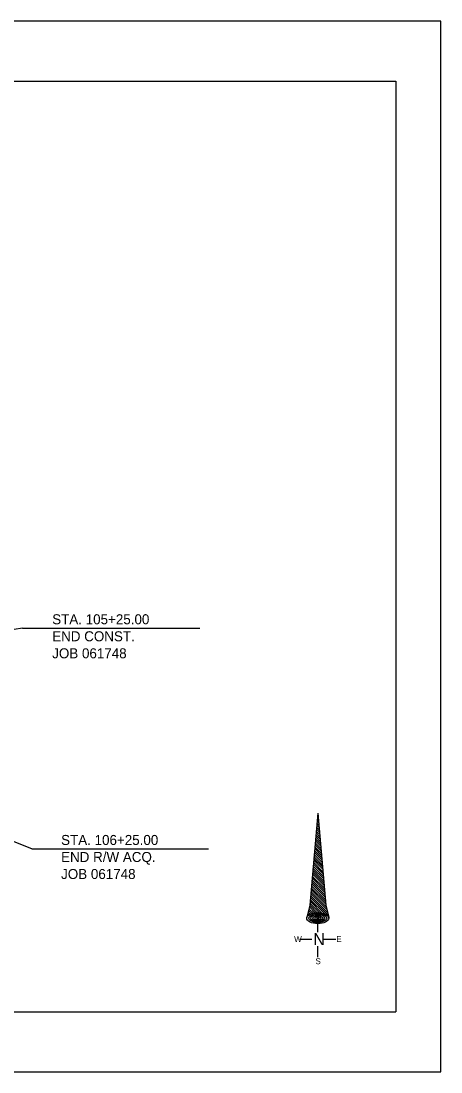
# Model space of a CAD drawing. Extents: x -3711 to 825, y -151 to 1050.
# Drawn here: x -2480 to -2061, y 0 to 1050 of the extents above; entities that cross this region are included whole.
import ezdxf

# ---------------------------------------------------------------- set-up
doc = ezdxf.new("R2010")
doc.units = 0
for name, color, linetype in [('E_Sheet Border', 7, 'Continuous'), ('E_Title Sheet', 7, 'Continuous'), ('R_Dimension', 7, 'Continuous'), ('R_No Plot', 7, 'Continuous')]:
    doc.layers.add(name, color=color, linetype=linetype)

msp = doc.modelspace()

# ---------------------------------------------------------------- linework, layer by layer
at = {"layer": 'E_Sheet Border'}
msp.add_lwpolyline([(-3710.7, 0), (-2060.7, 0), (-2060.7, 1050), (-3710.7, 1050)], close=True, dxfattribs=at)
at = {"layer": 'E_Title Sheet'}
for p, q in [((-2183.7, 258.7), (-2191.7, 166.7)), ((-2184.2, 252.4), (-2183, 251.3)), ((-2184.1, 254.4), (-2183.3, 253.6)), ((-2183.9, 256.3), (-2183.5, 255.9)), ((-2183.7, 258.7), (-2175.7, 166.7)), ((-2183.7, 258.3), (-2183.7, 258.2)), ((-2185.1, 242.7), (-2182, 239.6)), ((-2184.9, 244.6), (-2182.2, 242)), ((-2184.7, 246.6), (-2182.4, 244.3)), ((-2184.6, 248.5), (-2182.6, 246.6)), ((-2184.4, 250.5), (-2182.8, 248.9)), ((-2185.9, 232.9), (-2181, 228)), ((-2185.8, 234.9), (-2181.2, 230.3)), ((-2185.6, 236.8), (-2181.4, 232.7)), ((-2185.4, 238.8), (-2181.6, 235)), ((-2185.3, 240.7), (-2181.8, 237.3)), ((-2186.9, 221.2), (-2179.8, 214.1)), ((-2186.8, 223.2), (-2180, 216.4)), ((-2186.6, 225.1), (-2180.2, 218.7)), ((-2186.4, 227.1), (-2180.4, 221.1)), ((-2186.3, 229), (-2180.6, 223.4)), ((-2186.1, 231), (-2180.8, 225.7)), ((-2187.8, 211.5), (-2178.8, 202.5)), ((-2187.6, 213.4), (-2179, 204.8)), ((-2187.5, 215.4), (-2179.2, 207.1)), ((-2187.3, 217.3), (-2179.4, 209.4)), ((-2187.1, 219.3), (-2179.6, 211.8)), ((-2188.8, 199.7), (-2177.6, 188.5)), ((-2188.6, 201.7), (-2177.8, 190.8)), ((-2188.5, 203.7), (-2178, 193.2)), ((-2188.3, 205.6), (-2178.2, 195.5)), ((-2188.1, 207.6), (-2178.4, 197.8)), ((-2188, 209.5), (-2178.6, 200.1)), ((-2189.7, 190), (-2176.6, 176.9)), ((-2189.5, 191.9), (-2176.8, 179.2)), ((-2189.3, 193.9), (-2177, 181.6)), ((-2189.2, 195.8), (-2177.2, 183.9)), ((-2189, 197.8), (-2177.4, 186.2)), ((-2190.5, 180.2), (-2175.3, 165)), ((-2190.3, 182.2), (-2175.8, 167.6)), ((-2190.2, 184.1), (-2176, 169.9)), ((-2190, 186.1), (-2176.2, 172.3)), ((-2189.8, 188), (-2176.4, 174.6)), ((-2191.5, 168.5), (-2182.1, 159.1)), ((-2191.4, 170.5), (-2179.7, 158.8)), ((-2191.2, 172.4), (-2176.6, 157.9)), ((-2191, 174.4), (-2173.3, 156.7)), ((-2190.9, 176.3), (-2174, 159.5)), ((-2190.7, 178.3), (-2174.6, 162.2)), ((-2191.7, 166.7), (-2194.6, 154.2)), ((-2193.7, 158), (-2192.6, 156.9)), ((-2193.3, 159.7), (-2191.3, 157.6)), ((-2192.9, 161.4), (-2189.7, 158.2)), ((-2192.5, 163.1), (-2188.1, 158.7)), ((-2192.1, 164.9), (-2186.3, 159)), ((-2191.7, 166.6), (-2184.3, 159.1)), ((-2175.7, 166.7), (-2172.7, 154.2)), ((-2194.6, 154.6), (-2194.5, 154.6)), ((-2194.1, 156.3), (-2193.7, 155.9)), ((-2183.7, 139.7), (-2183.7, 153.7)), ((-2201.7, 132.7), (-2189.7, 132.7)), ((-2177.7, 132.7), (-2165.7, 132.7)), ((-2183.7, 114.7), (-2183.7, 125.7)), ((-3645.7, 60), (-2105.7, 60))]:
    msp.add_line(p, q, dxfattribs=at)
for points in [[(-3645.7, 990), (-2105.7, 990)], [(-2105.7, 990), (-2105.7, 60)]]:
    msp.add_lwpolyline(points, dxfattribs=at)
for major_axis in [(11, 0), (9, 0), (7, 0), (5, 0), (3, 0), (1, 0)]:
    msp.add_ellipse((-2183.7, 153.7), major_axis=major_axis, ratio=0.5, dxfattribs=at)
at = {"layer": 'R_Dimension'}
for p in [(-2478.4, 443.5), (-2469.4, 223.1)]:
    msp.add_line(p, (-2866.6, 379.8), dxfattribs=at)
for points in [[(-2478.4, 443.5), (-2301.6, 443.4)], [(-2469.4, 223.1), (-2292.7, 223)]]:
    msp.add_lwpolyline(points, dxfattribs=at)
at = {"layer": 'R_No Plot'}
msp.add_lwpolyline([(-3710.7, 0), (-2060.7, 0), (-2060.7, 1050), (-3710.7, 1050)], close=True, dxfattribs=at)

# ---------------------------------------------------------------- texts
at = {"layer": 'E_Title Sheet'}
for s, height, p in [('N', 12, (-2188.2, 126.7)), ('W', 6, (-2207.3, 129.7)), ('E', 6, (-2165.3, 129.7)), ('S', 6, (-2186, 107.7))]:
    msp.add_text(s, height=height, rotation=359.9924, dxfattribs=at).set_placement(p)
at = {"layer": 'R_Dimension'}
for s, p in [('STA. 105+25.00', (-2448.9, 447.3)), ('END CONST.', (-2448.9, 430.3)), ('JOB 061748', (-2448.9, 413.3)), ('STA. 106+25.00', (-2440, 226.8)), ('END R/W ACQ.', (-2440, 209.8)), ('JOB 061748', (-2440, 192.8))]:
    msp.add_text(s, height=10, rotation=359.9994, dxfattribs=at).set_placement(p)

doc.saveas('drawing.dxf')
